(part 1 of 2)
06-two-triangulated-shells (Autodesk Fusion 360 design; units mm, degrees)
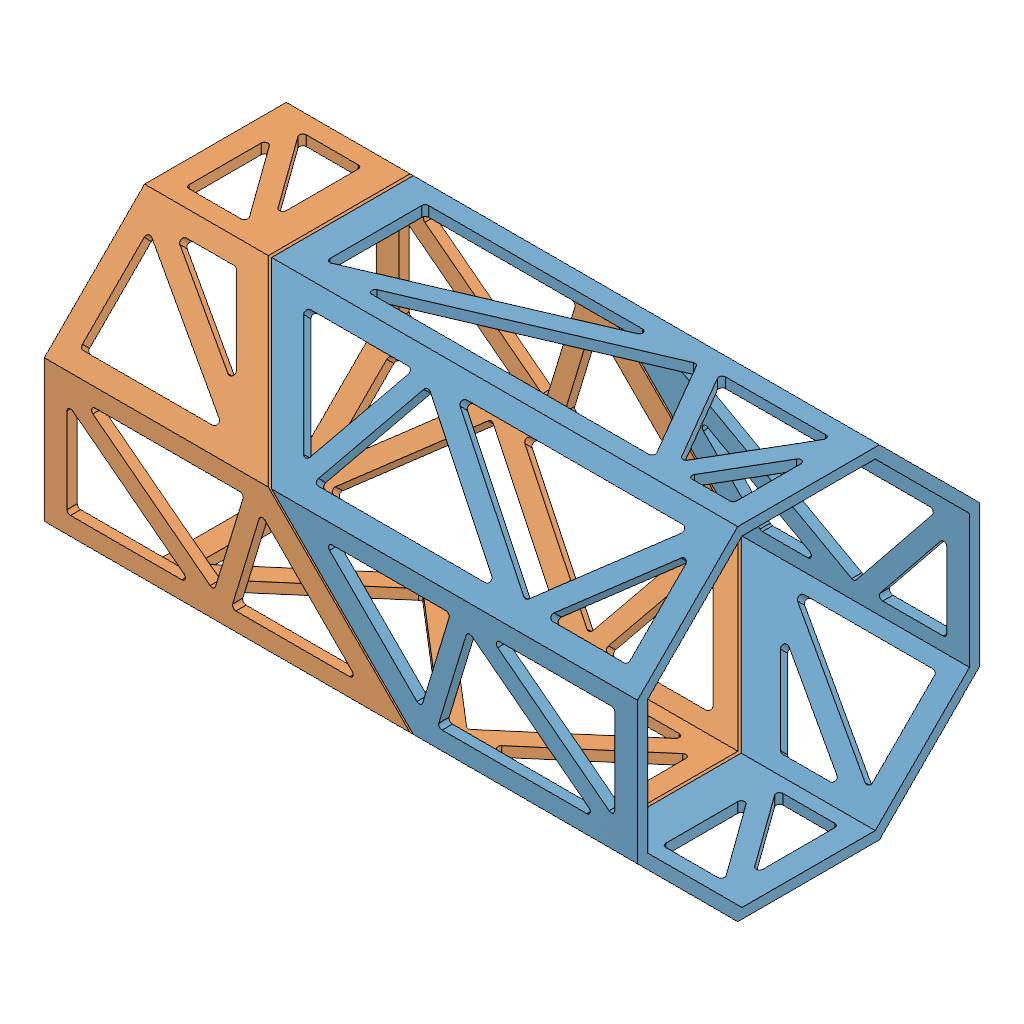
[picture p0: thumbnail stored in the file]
part number: 2026-11-02-20-17-55-344
part number: 2026-11-02-20-17-59-218
part number: 2026-11-02-20-17-59-224
parameter "bodyWidth" = 150 comment "Regular octagon across flats; corner diameter is larger."
parameter "bodyLength" = 260 comment "Overall straight length of the shared master blank."
parameter "splitAngle" = 45 comment "Keep this lesson angle at45 degrees."
parameter "faceGap" = 1 comment "Gap between the two printed joint faces."
parameter "wall" = 4.5 comment "Integrated shell and side brace radial thickness."
parameter "faceHalfWidth" = 31.066 (= "bodyWidth * ( sqrt(2) - 1 ) / 2") comment "Half-width of each outer planar facet."
parameter "memberWidth" = 8 comment "Nominal brace and corner chord width in a facet."
parameter "nodeHalfWidth" = 27.066 (= "faceHalfWidth - memberWidth / 2") comment "Chord centerlines measured from facet center."
parameter "jointNodeQ" = 7 comment "First truss skeleton row from the center joint plane."
parameter "endRim" = 10 comment "Uncut axial rim at each distant end."
parameter "endNodeX" = 124 (= "bodyLength / 2 - endRim + memberWidth / 2") comment "Last skeleton row before aperture inset."
parameter "apertureRadius" = 1.5 comment "Rounded internal corners at triangular openings."
parameter "spokeWidth" = 10 comment "Width of each deep bearing bulkhead spoke."
parameter "spokeDepth" = 18 comment "Bulkhead depth normal to the diagonal joint face."
parameter "carrierOD" = 52 comment "Outside of integrated A front bearing carrier."
parameter "rearCarrierClearance" = 46 comment "Internal carrier relief above front bearing shoulder."
parameter "tubeCornerChamfer" = 0.5 comment "Exposed outside octagon corner bevel."
parameter "tubeRimChamfer" = 0.3 comment "End rim and print-contact edge relief."
parameter "cordStation" = 125 (= "bodyLength / 2 - endRim / 2") comment "Load-test cord port center measured along body X."
parameter "bearingOD" = 22 comment "608 measured outside diameter."
parameter "bearingID" = 8 comment "608 bore."
parameter "bearingWidth" = 7 comment "608 width."
parameter "seatAllowance" = 0.2 comment "Trial DIAMETRAL clearance; choose with printed coupon."
parameter "seatDiameter" = 22.2 (= "bearingOD + seatAllowance") comment "Measured fit controls this."
parameter "coreOD" = 44 comment "Bearing holder outer diameter."
parameter "raceRelief" = 19.5 comment "Outer-ring shoulder opening; verify seals."
parameter "frontSeatDepth" = 7.1 comment "0.1 mm outer-ring axial allowance."
parameter "rearSeatDepth" = 7.2 comment "0.2 mm outer-ring axial float."
parameter "shoulder" = 3 comment "Backing behind each bearing seat."
parameter "supportSpacer" = 12 comment "Purchased metal M3 spacer length."
parameter "supportCircle" = 34 comment "Three M3 support bolts."
parameter "supportSpacerOD" = 6 comment "Purchased spacer outside diameter."
parameter "capThickness" = 3 comment "Both printed outer-ring retaining caps."
parameter "m3Clearance" = 3.3 comment "M3 through holes."
parameter "m4Clearance" = 4.3 comment "M4 through holes."
parameter "qFront" = 0.5 (= "faceGap / 2") comment "Front bearing starts at A mating face."
parameter "qFrontBack" = 10.6 (= "qFront + frontSeatDepth + shoulder") comment "End of integrated A holder."
parameter "qRearBase" = 22.6 (= "qFrontBack + supportSpacer") comment "Start of removable rear holder."
parameter "qRearBearing" = 25.6 (= "qRearBase + shoulder") comment "Rear bearing inner end."
parameter "qRearEnd" = 32.8 (= "qRearBearing + rearSeatDepth") comment "Rear holder outer end."
parameter "bearingSpacing" = 25.1 (= "qRearBearing - qFront") comment "Derived support-center spacing, not a bearing rating."
parameter "mountOD" = 76 comment "B mount and F flange outside diameter."
parameter "mountCircle" = 64 comment "Four M4 attachment holes."
parameter "mountOpening" = 50.3 comment "B through opening."
parameter "hubFace" = -23 comment "Metal hub flat mounting face."
parameter "adapterThickness" = 6 comment "F flange and metal compression sleeve length."
parameter "pilotDiameter" = 50 comment "F shallow centering pilot."
parameter "pilotInside" = 34 comment "Clearance around metal hub."
parameter "pilotHeight" = 2 comment "Short pilot only."
parameter "hubHoleSpacing" = 16 comment "Metal Sonic hub square hole spacing."
parameter "sleeveOD" = 8 comment "M4 metal compression sleeves."
parameter "sleeveAllowance" = 0.2 comment "Trial DIAMETRAL sleeve clearance."
parameter "shaftClearance" = 8.5 comment "F clearance hole; not a bearing."
parameter "nutAF" = 7.2 comment "M4 nominal 7 AF nut trial pocket."
parameter "nutDepth" = 4 comment "Open front M4 nut pocket."
parameter "rootRadius" = 1 comment "Hub-to-wall blend."
parameter "entryChamfer" = 0.4 comment "Assembly lead-in."
parameter "bedRelief" = 0.3 comment "Bed-contact edge allowance."
sketch "01 Master Octagon" plane through (0, 0, 0) normal (1, 0, 0) x axis (0, 0, -1)
  line L1 (31.066, 75) -> (75, 31.066)
  line L2 (-31.066, 75) -> (31.066, 75)
  line L3 (-75, 31.066) -> (-31.066, 75)
  line L4 (-75, -31.066) -> (-75, 31.066)
  line L5 (-31.066, -75) -> (-75, -31.066)
  line L6 (31.066, -75) -> (-31.066, -75)
  line L7 (75, -31.066) -> (31.066, -75)
  line L8 (75, 31.066) -> (75, -31.066)
  point P1 (0, 0)
  point P10 (0, 0)
  point P3 (31.066, 75)
  point P8 (31.066, -75)
  coincident P1 P10
  horizontal L2
  dimension "d59" distance P3 P8 = 150 (= "bodyWidth")
extrude "Extrude1" new body sketch "01 Master Octagon" distance 260 (= "bodyLength")
work_plane "WorkPlane1" RotateAngle 45 (= "splitAngle") ExtraOffset 0
split "Split1"
offset_faces "OffsetFaces1" distance -0.5 (= "-faceGap / 2")
offset_faces "OffsetFaces2" distance -0.5 (= "-faceGap / 2")
component_from_bodies "Body->Comp1"
component_from_bodies "Body->Comp2"
shell "Shell1" innerThickness 4.5 (= "wall")
shell "Shell1" innerThickness 4.5 (= "wall")
work_plane "WorkPlane1" RotateAngle -90 ExtraOffset 0
work_plane "WorkPlane2" AlongDistance 75 (= "bodyWidth / 2") ExtraOffset 0
sketch "A Facet 0 Triangle 1" plane through (0, 75, 0) normal (0, 1, 0) x axis (1, 0, 0)
  line L1 (-65.1005, -27.066) -> (-65.1005, 27.066)
  line L2 (60.9665, 27.066) -> (-65.1005, -27.066)
  line L3 (-65.1005, 27.066) -> (60.9665, 27.066)
  line L4 (-61.1005, -20.9953) -> (-61.1005, 23.066)
  line L5 (41.513, 23.066) -> (-61.1005, -20.9953)
  line L6 (-61.1005, 23.066) -> (41.513, 23.066)
  point P1 (0, 0)
  point P2 (-65.1005, 27.066)
  point P3 (-65.1005, -27.066)
  point P4 (60.9665, 27.066)
  dimension "d72" distance P1 P2 = 65.1005 (= "Linear Dimension-2")
  dimension "d73" distance P1 P2 = 27.066 (= "Linear Dimension-3")
  dimension "d74" distance P1 P3 = 65.1005 (= "Linear Dimension-4")
  dimension "d75" distance P1 P3 = 27.066 (= "Linear Dimension-5")
  dimension "d76" distance P1 P4 = 60.9665 (= "Linear Dimension-6")
  dimension "d77" distance P1 P4 = 27.066 (= "Linear Dimension-7")
  dimension "d78" = -4 (= "-memberWidth / 2")
extrude "Extrude1" cut sketch "A Facet 0 Triangle 1" profile of L5 L6 L4 against normal blind 4.7 (magnitude of "-( wall + 0.2 mm )")
sketch "A Facet 0 Triangle 2" plane through (0, 75, 0) normal (0, 1, 0) x axis (1, 0, 0)
  line L1 (60.9665, 27.066) -> (-65.1005, -27.066)
  line L2 (92.4832, -27.066) -> (60.9665, 27.066)
  line L3 (-65.1005, -27.066) -> (92.4832, -27.066)
  line L4 (59.2912, 21.9935) -> (-45.647, -23.066)
  line L5 (85.5258, -23.066) -> (59.2912, 21.9935)
  line L6 (-45.647, -23.066) -> (85.5258, -23.066)
  point P1 (0, 0)
  point P2 (-65.1005, -27.066)
  point P3 (60.9665, 27.066)
  point P4 (92.4832, -27.066)
  dimension "d81" distance P1 P2 = 65.1005 (= "Linear Dimension-2")
  dimension "d82" distance P1 P2 = 27.066 (= "Linear Dimension-3")
  dimension "d83" distance P1 P3 = 60.9665 (= "Linear Dimension-4")
  dimension "d84" distance P1 P3 = 27.066 (= "Linear Dimension-5")
  dimension "d85" distance P1 P4 = 92.4832 (= "Linear Dimension-6")
  dimension "d86" distance P1 P4 = 27.066 (= "Linear Dimension-7")
  dimension "d87" = 4 (= "memberWidth / 2")
extrude "Extrude2" cut sketch "A Facet 0 Triangle 2" profile of L5 L6 L4 against normal blind 4.7 (magnitude of "-( wall + 0.2 mm )")
sketch "A Facet 0 Triangle 3" plane through (0, 75, 0) normal (0, 1, 0) x axis (1, 0, 0)
  line L1 (92.4832, -27.066) -> (60.9665, 27.066)
  line L2 (124, 27.066) -> (92.4832, -27.066)
  line L3 (60.9665, 27.066) -> (124, 27.066)
  line L4 (92.4832, -19.1161) -> (67.924, 23.066)
  line L5 (117.0425, 23.066) -> (92.4832, -19.1161)
  line L6 (67.924, 23.066) -> (117.0425, 23.066)
  point P1 (0, 0)
  point P2 (60.9665, 27.066)
  point P3 (92.4832, -27.066)
  point P4 (124, 27.066)
  dimension "d90" distance P1 P2 = 60.9665 (= "Linear Dimension-2")
  dimension "d91" distance P1 P2 = 27.066 (= "Linear Dimension-3")
  dimension "d92" distance P1 P3 = 92.4832 (= "Linear Dimension-4")
  dimension "d93" distance P1 P3 = 27.066 (= "Linear Dimension-5")
  dimension "d94" distance P1 P4 = 124 (= "Linear Dimension-6")
  dimension "d95" distance P1 P4 = 27.066 (= "Linear Dimension-7")
  dimension "d96" = -4 (= "-memberWidth / 2")
extrude "Extrude3" cut sketch "A Facet 0 Triangle 3" profile of L5 L6 L4 against normal blind 4.7 (magnitude of "-( wall + 0.2 mm )")
sketch "A Facet 0 Triangle 4" plane through (0, 75, 0) normal (0, 1, 0) x axis (1, 0, 0)
  line L1 (124, 27.066) -> (92.4832, -27.066)
  line L2 (124, -27.066) -> (124, 27.066)
  line L3 (92.4832, -27.066) -> (124, -27.066)
  line L4 (120, 12.2459) -> (99.4407, -23.066)
  line L5 (120, -23.066) -> (120, 12.2459)
  line L6 (99.4407, -23.066) -> (120, -23.066)
  point P1 (0, 0)
  point P2 (92.4832, -27.066)
  point P3 (124, 27.066)
  point P4 (124, -27.066)
  dimension "d99" distance P1 P2 = 92.4832 (= "Linear Dimension-2")
  dimension "d100" distance P1 P2 = 27.066 (= "Linear Dimension-3")
  dimension "d101" distance P1 P3 = 124 (= "Linear Dimension-4")
  dimension "d102" distance P1 P3 = 27.066 (= "Linear Dimension-5")
  dimension "d103" distance P1 P4 = 124 (= "Linear Dimension-6")
  dimension "d104" distance P1 P4 = 27.066 (= "Linear Dimension-7")
  dimension "d105" = 4 (= "memberWidth / 2")
extrude "Extrude4" cut sketch "A Facet 0 Triangle 4" profile of L5 L6 L4 against normal blind 4.7 (magnitude of "-( wall + 0.2 mm )")
fillet "Fillet1" radius 1.5 (= "apertureRadius")
work_plane "WorkPlane3" RotateAngle -45 ExtraOffset 0
work_plane "WorkPlane4" AlongDistance 75 (= "bodyWidth / 2") ExtraOffset 0
sketch "A Facet 45 Triangle 1" plane through (0, 53.033, 53.033) normal (0, 0.7071, 0.7071) x axis (1, 0, 0)
  line L1 (-23.9949, -27.066) -> (-62.2721, 27.066)
  line L2 (-0.1814, 27.066) -> (-23.9949, -27.066)
  line L3 (-62.2721, 27.066) -> (-0.1814, 27.066)
  line L4 (-24.81, -18.9852) -> (-54.5447, 23.066)
  line L5 (-6.311, 23.066) -> (-24.81, -18.9852)
  line L6 (-54.5447, 23.066) -> (-6.311, 23.066)
  point P1 (0, 0)
  point P2 (-62.2721, 27.066)
  point P3 (-23.9949, -27.066)
  point P4 (-0.1814, 27.066)
  dimension "d114" distance P1 P2 = 62.2721 (= "Linear Dimension-2")
  dimension "d115" distance P1 P2 = 27.066 (= "Linear Dimension-3")
  dimension "d116" distance P1 P3 = 23.9949 (= "Linear Dimension-4")
  dimension "d117" distance P1 P3 = 27.066 (= "Linear Dimension-5")
  dimension "d118" distance P1 P4 = 0.1814 (= "Linear Dimension-6")
  dimension "d119" distance P1 P4 = 27.066 (= "Linear Dimension-7")
  dimension "d120" = -4 (= "-memberWidth / 2")
extrude "Extrude5" cut sketch "A Facet 45 Triangle 1" profile of L5 L6 L4 against normal blind 4.7 (magnitude of "-( wall + 0.2 mm )")
sketch "A Facet 45 Triangle 2" plane through (0, 53.033, 53.033) normal (0, 0.7071, 0.7071) x axis (1, 0, 0)
  line L1 (-0.1814, 27.066) -> (-23.9949, -27.066)
  line L2 (74.6684, -27.066) -> (-0.1814, 27.066)
  line L3 (-23.9949, -27.066) -> (74.6684, -27.066)
  line L4 (1.4863, 20.9235) -> (-17.8653, -23.066)
  line L5 (62.3117, -23.066) -> (1.4863, 20.9235)
  line L6 (-17.8653, -23.066) -> (62.3117, -23.066)
  point P1 (0, 0)
  point P2 (-23.9949, -27.066)
  point P3 (-0.1814, 27.066)
  point P4 (74.6684, -27.066)
  dimension "d123" distance P1 P2 = 23.9949 (= "Linear Dimension-2")
  dimension "d124" distance P1 P2 = 27.066 (= "Linear Dimension-3")
  dimension "d125" distance P1 P3 = 0.1814 (= "Linear Dimension-4")
  dimension "d126" distance P1 P3 = 27.066 (= "Linear Dimension-5")
  dimension "d127" distance P1 P4 = 74.6684 (= "Linear Dimension-6")
  dimension "d128" distance P1 P4 = 27.066 (= "Linear Dimension-7")
  dimension "d129" = 4 (= "memberWidth / 2")
extrude "Extrude6" cut sketch "A Facet 45 Triangle 2" profile of L5 L6 L4 against normal blind 4.7 (magnitude of "-( wall + 0.2 mm )")
sketch "A Facet 45 Triangle 3" plane through (0, 53.033, 53.033) normal (0, 0.7071, 0.7071) x axis (1, 0, 0)
  line L1 (74.6684, -27.066) -> (-0.1814, 27.066)
  line L2 (124, 27.066) -> (74.6684, -27.066)
  line L3 (-0.1814, 27.066) -> (124, 27.066)
  line L4 (74.1179, -21.7315) -> (12.1753, 23.066)
  line L5 (114.9429, 23.066) -> (74.1179, -21.7315)
  line L6 (12.1753, 23.066) -> (114.9429, 23.066)
  point P1 (0, 0)
  point P2 (-0.1814, 27.066)
  point P3 (74.6684, -27.066)
  point P4 (124, 27.066)
  dimension "d132" distance P1 P2 = 0.1814 (= "Linear Dimension-2")
  dimension "d133" distance P1 P2 = 27.066 (= "Linear Dimension-3")
  dimension "d134" distance P1 P3 = 74.6684 (= "Linear Dimension-4")
  dimension "d135" distance P1 P3 = 27.066 (= "Linear Dimension-5")
  dimension "d136" distance P1 P4 = 124 (= "Linear Dimension-6")
  dimension "d137" distance P1 P4 = 27.066 (= "Linear Dimension-7")
  dimension "d138" = -4 (= "-memberWidth / 2")
extrude "Extrude7" cut sketch "A Facet 45 Triangle 3" profile of L5 L6 L4 against normal blind 4.7 (magnitude of "-( wall + 0.2 mm )")
sketch "A Facet 45 Triangle 4" plane through (0, 53.033, 53.033) normal (0, 0.7071, 0.7071) x axis (1, 0, 0)
  line L1 (124, 27.066) -> (74.6684, -27.066)
  line L2 (124, -27.066) -> (124, 27.066)
  line L3 (74.6684, -27.066) -> (124, -27.066)
  line L4 (120, 16.7383) -> (83.7255, -23.066)
  line L5 (120, -23.066) -> (120, 16.7383)
  line L6 (83.7255, -23.066) -> (120, -23.066)
  point P1 (0, 0)
  point P2 (74.6684, -27.066)
  point P3 (124, 27.066)
  point P4 (124, -27.066)
  dimension "d141" distance P1 P2 = 74.6684 (= "Linear Dimension-2")
  dimension "d142" distance P1 P2 = 27.066 (= "Linear Dimension-3")
  dimension "d143" distance P1 P3 = 124 (= "Linear Dimension-4")
  dimension "d144" distance P1 P3 = 27.066 (= "Linear Dimension-5")
  dimension "d145" distance P1 P4 = 124 (= "Linear Dimension-6")
  dimension "d146" distance P1 P4 = 27.066 (= "Linear Dimension-7")
  dimension "d147" = 4 (= "memberWidth / 2")
extrude "Extrude8" cut sketch "A Facet 45 Triangle 4" profile of L5 L6 L4 against normal blind 4.7 (magnitude of "-( wall + 0.2 mm )")
fillet "Fillet2" radius 1.5 (= "apertureRadius")
work_plane "WorkPlane5" RotateAngle 0 ExtraOffset 0
work_plane "WorkPlane6" AlongDistance 75 (= "bodyWidth / 2") ExtraOffset 0
sketch "A Facet 90 Triangle 1" plane through (0, 0, 75) normal (0, 0, 1) x axis (1, 0, 0)
  line L1 (36.9655, -27.066) -> (-17.1665, 27.066)
  line L2 (53.4167, 27.066) -> (36.9655, -27.066)
  line L3 (-17.1665, 27.066) -> (53.4167, 27.066)
  line L4 (35.0777, -19.5214) -> (-7.5097, 23.066)
  line L5 (48.0205, 23.066) -> (35.0777, -19.5214)
  line L6 (-7.5097, 23.066) -> (48.0205, 23.066)
  point P1 (0, 0)
  point P2 (-17.1665, 27.066)
  point P3 (36.9655, -27.066)
  point P4 (53.4167, 27.066)
  dimension "d156" distance P1 P2 = 17.1665 (= "Linear Dimension-2")
  dimension "d157" distance P1 P2 = 27.066 (= "Linear Dimension-3")
  dimension "d158" distance P1 P3 = 36.9655 (= "Linear Dimension-4")
  dimension "d159" distance P1 P3 = 27.066 (= "Linear Dimension-5")
  dimension "d160" distance P1 P4 = 53.4167 (= "Linear Dimension-6")
  dimension "d161" distance P1 P4 = 27.066 (= "Linear Dimension-7")
  dimension "d162" = -4 (= "-memberWidth / 2")
extrude "Extrude9" cut sketch "A Facet 90 Triangle 1" profile of L5 L6 L4 against normal blind 4.7 (magnitude of "-( wall + 0.2 mm )")
sketch "A Facet 90 Triangle 2" plane through (0, 0, 75) normal (0, 0, 1) x axis (1, 0, 0)
  line L1 (53.4167, 27.066) -> (36.9655, -27.066)
  line L2 (124, -27.066) -> (53.4167, 27.066)
  line L3 (36.9655, -27.066) -> (124, -27.066)
  line L4 (55.5648, 20.3777) -> (42.3618, -23.066)
  line L5 (112.2115, -23.066) -> (55.5648, 20.3777)
  line L6 (42.3618, -23.066) -> (112.2115, -23.066)
  point P1 (0, 0)
  point P2 (36.9655, -27.066)
  point P3 (53.4167, 27.066)
  point P4 (124, -27.066)
  dimension "d165" distance P1 P2 = 36.9655 (= "Linear Dimension-2")
  dimension "d166" distance P1 P2 = 27.066 (= "Linear Dimension-3")
  dimension "d167" distance P1 P3 = 53.4167 (= "Linear Dimension-4")
  dimension "d168" distance P1 P3 = 27.066 (= "Linear Dimension-5")
  dimension "d169" distance P1 P4 = 124 (= "Linear Dimension-6")
  dimension "d170" distance P1 P4 = 27.066 (= "Linear Dimension-7")
  dimension "d171" = 4 (= "memberWidth / 2")
extrude "Extrude10" cut sketch "A Facet 90 Triangle 2" profile of L5 L6 L4 against normal blind 4.7 (magnitude of "-( wall + 0.2 mm )")
sketch "A Facet 90 Triangle 3" plane through (0, 0, 75) normal (0, 0, 1) x axis (1, 0, 0)
  line L1 (124, -27.066) -> (53.4167, 27.066)
  line L2 (124, 27.066) -> (124, -27.066)
  line L3 (53.4167, 27.066) -> (124, 27.066)
  line L4 (120, -18.9574) -> (65.2053, 23.066)
  line L5 (120, 23.066) -> (120, -18.9574)
  line L6 (65.2053, 23.066) -> (120, 23.066)
  point P1 (0, 0)
  point P2 (53.4167, 27.066)
  point P3 (124, -27.066)
  point P4 (124, 27.066)
  dimension "d174" distance P1 P2 = 53.4167 (= "Linear Dimension-2")
  dimension "d175" distance P1 P2 = 27.066 (= "Linear Dimension-3")
  dimension "d176" distance P1 P3 = 124 (= "Linear Dimension-4")
  dimension "d177" distance P1 P3 = 27.066 (= "Linear Dimension-5")
  dimension "d178" distance P1 P4 = 124 (= "Linear Dimension-6")
  dimension "d179" distance P1 P4 = 27.066 (= "Linear Dimension-7")
  dimension "d180" = -4 (= "-memberWidth / 2")
extrude "Extrude11" cut sketch "A Facet 90 Triangle 3" profile of L5 L6 L4 against normal blind 4.7 (magnitude of "-( wall + 0.2 mm )")
fillet "Fillet3" radius 1.5 (= "apertureRadius")
work_plane "WorkPlane7" RotateAngle 45 ExtraOffset 0
work_plane "WorkPlane8" AlongDistance 75 (= "bodyWidth / 2") ExtraOffset 0
sketch "A Facet 135 Triangle 1" plane through (0, -53.033, 53.033) normal (0, -0.7071, 0.7071) x axis (1, 0, 0)
  line L1 (82.0711, -27.066) -> (43.7939, 27.066)
  line L2 (124, 27.066) -> (82.0711, -27.066)
  line L3 (43.7939, 27.066) -> (124, 27.066)
  line L4 (82.2175, -20.3449) -> (51.5213, 23.066)
  line L5 (115.8422, 23.066) -> (82.2175, -20.3449)
  line L6 (51.5213, 23.066) -> (115.8422, 23.066)
  point P1 (0, 0)
  point P2 (43.7939, 27.066)
  point P3 (82.0711, -27.066)
  point P4 (124, 27.066)
  dimension "d189" distance P1 P2 = 43.7939 (= "Linear Dimension-2")
  dimension "d190" distance P1 P2 = 27.066 (= "Linear Dimension-3")
  dimension "d191" distance P1 P3 = 82.0711 (= "Linear Dimension-4")
  dimension "d192" distance P1 P3 = 27.066 (= "Linear Dimension-5")
  dimension "d193" distance P1 P4 = 124 (= "Linear Dimension-6")
  dimension "d194" distance P1 P4 = 27.066 (= "Linear Dimension-7")
  dimension "d195" = -4 (= "-memberWidth / 2")
extrude "Extrude12" cut sketch "A Facet 135 Triangle 1" profile of L5 L6 L4 against normal blind 4.7 (magnitude of "-( wall + 0.2 mm )")
sketch "A Facet 135 Triangle 2" plane through (0, -53.033, 53.033) normal (0, -0.7071, 0.7071) x axis (1, 0, 0)
  line L1 (124, 27.066) -> (82.0711, -27.066)
  line L2 (124, -27.066) -> (124, 27.066)
  line L3 (82.0711, -27.066) -> (124, -27.066)
  line L4 (120, 15.3697) -> (90.2289, -23.066)
  line L5 (120, -23.066) -> (120, 15.3697)
  line L6 (90.2289, -23.066) -> (120, -23.066)
  point P1 (0, 0)
  point P2 (82.0711, -27.066)
  point P3 (124, 27.066)
  point P4 (124, -27.066)
  dimension "d198" distance P1 P2 = 82.0711 (= "Linear Dimension-2")
  dimension "d199" distance P1 P2 = 27.066 (= "Linear Dimension-3")
  dimension "d200" distance P1 P3 = 124 (= "Linear Dimension-4")
  dimension "d201" distance P1 P3 = 27.066 (= "Linear Dimension-5")
  dimension "d202" distance P1 P4 = 124 (= "Linear Dimension-6")
  dimension "d203" distance P1 P4 = 27.066 (= "Linear Dimension-7")
  dimension "d204" = 4 (= "memberWidth / 2")
extrude "Extrude13" cut sketch "A Facet 135 Triangle 2" profile of L5 L6 L4 against normal blind 4.7 (magnitude of "-( wall + 0.2 mm )")
fillet "Fillet4" radius 1.5 (= "apertureRadius")
work_plane "WorkPlane9" RotateAngle 90 ExtraOffset 0
work_plane "WorkPlane10" AlongDistance 75 (= "bodyWidth / 2") ExtraOffset 0
sketch "A Facet 180 Triangle 1" plane through (0, -75, 0) normal (0, -1, 0) x axis (-1, 0, 0)
  line L1 (-84.8995, 27.066) -> (-84.8995, -27.066)
  line L2 (-124, -27.066) -> (-84.8995, 27.066)
  line L3 (-84.8995, -27.066) -> (-124, -27.066)
  line L4 (-88.8995, 14.697) -> (-88.8995, -23.066)
  line L5 (-116.1764, -23.066) -> (-88.8995, 14.697)
  line L6 (-88.8995, -23.066) -> (-116.1764, -23.066)
  point P1 (0, 0)
  point P2 (-84.8995, -27.066)
  point P3 (-84.8995, 27.066)
  point P4 (-124, -27.066)
  dimension "d213" distance P1 P2 = 84.8995 (= "Linear Dimension-2")
  dimension "d214" distance P1 P2 = 27.066 (= "Linear Dimension-3")
  dimension "d215" distance P1 P3 = 84.8995 (= "Linear Dimension-4")
  dimension "d216" distance P1 P3 = 27.066 (= "Linear Dimension-5")
  dimension "d217" distance P1 P4 = 124 (= "Linear Dimension-6")
  dimension "d218" distance P1 P4 = 27.066 (= "Linear Dimension-7")
  dimension "d219" = -4 (= "-memberWidth / 2")
extrude "Extrude14" cut sketch "A Facet 180 Triangle 1" profile of L5 L6 L4 against normal blind 4.7 (magnitude of "-( wall + 0.2 mm )")
sketch "A Facet 180 Triangle 2" plane through (0, -75, 0) normal (0, -1, 0) x axis (-1, 0, 0)
  line L1 (-124, -27.066) -> (-84.8995, 27.066)
  line L2 (-124, 27.066) -> (-124, -27.066)
  line L3 (-84.8995, 27.066) -> (-124, 27.066)
  line L4 (-120, -14.697) -> (-92.7231, 23.066)
  line L5 (-120, 23.066) -> (-120, -14.697)
  line L6 (-92.7231, 23.066) -> (-120, 23.066)
  point P1 (0, 0)
  point P2 (-84.8995, 27.066)
  point P3 (-124, -27.066)
  point P4 (-124, 27.066)
  dimension "d222" distance P1 P2 = 84.8995 (= "Linear Dimension-2")
  dimension "d223" distance P1 P2 = 27.066 (= "Linear Dimension-3")
  dimension "d224" distance P1 P3 = 124 (= "Linear Dimension-4")
  dimension "d225" distance P1 P3 = 27.066 (= "Linear Dimension-5")
  dimension "d226" distance P1 P4 = 124 (= "Linear Dimension-6")
  dimension "d227" distance P1 P4 = 27.066 (= "Linear Dimension-7")
  dimension "d228" = 4 (= "memberWidth / 2")
extrude "Extrude15" cut sketch "A Facet 180 Triangle 2" profile of L5 L6 L4 against normal blind 4.7 (magnitude of "-( wall + 0.2 mm )")
fillet "Fillet5" radius 1.5 (= "apertureRadius")
work_plane "WorkPlane11" RotateAngle 135 ExtraOffset 0
work_plane "WorkPlane12" AlongDistance 75 (= "bodyWidth / 2") ExtraOffset 0
sketch "A Facet 225 Triangle 1" plane through (0, -53.033, -53.033) normal (0, -0.7071, -0.7071) x axis (1, 0, 0)
  line L1 (43.7939, -27.066) -> (82.0711, 27.066)
  line L2 (124, 27.066) -> (43.7939, -27.066)
  line L3 (82.0711, 27.066) -> (124, 27.066)
  line L4 (59.6927, -11.51) -> (84.1416, 23.066)
  line L5 (110.9231, 23.066) -> (59.6927, -11.51)
  line L6 (84.1416, 23.066) -> (110.9231, 23.066)
  point P1 (0, 0)
  point P2 (82.0711, 27.066)
  point P3 (43.7939, -27.066)
  point P4 (124, 27.066)
  dimension "d237" distance P1 P2 = 82.0711 (= "Linear Dimension-2")
  dimension "d238" distance P1 P2 = 27.066 (= "Linear Dimension-3")
  dimension "d239" distance P1 P3 = 43.7939 (= "Linear Dimension-4")
  dimension "d240" distance P1 P3 = 27.066 (= "Linear Dimension-5")
  dimension "d241" distance P1 P4 = 124 (= "Linear Dimension-6")
  dimension "d242" distance P1 P4 = 27.066 (= "Linear Dimension-7")
  dimension "d243" = -4 (= "-memberWidth / 2")
extrude "Extrude16" cut sketch "A Facet 225 Triangle 1" profile of L5 L6 L4 against normal blind 4.7 (magnitude of "-( wall + 0.2 mm )")
sketch "A Facet 225 Triangle 2" plane through (0, -53.033, -53.033) normal (0, -0.7071, -0.7071) x axis (1, 0, 0)
  line L1 (124, 27.066) -> (43.7939, -27.066)
  line L2 (124, -27.066) -> (124, 27.066)
  line L3 (43.7939, -27.066) -> (124, -27.066)
  line L4 (120, 19.5406) -> (56.8709, -23.066)
  line L5 (120, -23.066) -> (120, 19.5406)
  line L6 (56.8709, -23.066) -> (120, -23.066)
  point P1 (0, 0)
  point P2 (43.7939, -27.066)
  point P3 (124, 27.066)
  point P4 (124, -27.066)
  dimension "d246" distance P1 P2 = 43.7939 (= "Linear Dimension-2")
  dimension "d247" distance P1 P2 = 27.066 (= "Linear Dimension-3")
  dimension "d248" distance P1 P3 = 124 (= "Linear Dimension-4")
  dimension "d249" distance P1 P3 = 27.066 (= "Linear Dimension-5")
  dimension "d250" distance P1 P4 = 124 (= "Linear Dimension-6")
  dimension "d251" distance P1 P4 = 27.066 (= "Linear Dimension-7")
  dimension "d252" = 4 (= "memberWidth / 2")
extrude "Extrude17" cut sketch "A Facet 225 Triangle 2" profile of L5 L6 L4 against normal blind 4.7 (magnitude of "-( wall + 0.2 mm )")
fillet "Fillet6" radius 1.5 (= "apertureRadius")
work_plane "WorkPlane13" RotateAngle 180 ExtraOffset 0
work_plane "WorkPlane14" AlongDistance 75 (= "bodyWidth / 2") ExtraOffset 0
sketch "A Facet 270 Triangle 1" plane through (0, 0, -75) normal (0, 0, -1) x axis (-1, 0, 0)
  line L1 (17.1665, 27.066) -> (-36.9655, -27.066)
  line L2 (-80.4828, -27.066) -> (17.1665, 27.066)
  line L3 (-36.9655, -27.066) -> (-80.4828, -27.066)
  line L4 (-5.7896, 9.7668) -> (-38.6224, -23.066)
  line L5 (-65.0169, -23.066) -> (-5.7896, 9.7668)
  line L6 (-38.6224, -23.066) -> (-65.0169, -23.066)
  point P1 (0, 0)
  point P2 (-36.9655, -27.066)
  point P3 (17.1665, 27.066)
  point P4 (-80.4828, -27.066)
  dimension "d261" distance P1 P2 = 36.9655 (= "Linear Dimension-2")
  dimension "d262" distance P1 P2 = 27.066 (= "Linear Dimension-3")
  dimension "d263" distance P1 P3 = 17.1665 (= "Linear Dimension-4")
  dimension "d264" distance P1 P3 = 27.066 (= "Linear Dimension-5")
  dimension "d265" distance P1 P4 = 80.4828 (= "Linear Dimension-6")
  dimension "d266" distance P1 P4 = 27.066 (= "Linear Dimension-7")
  dimension "d267" = -4 (= "-memberWidth / 2")
extrude "Extrude18" cut sketch "A Facet 270 Triangle 1" profile of L5 L6 L4 against normal blind 4.7 (magnitude of "-( wall + 0.2 mm )")
sketch "A Facet 270 Triangle 2" plane through (0, 0, -75) normal (0, 0, -1) x axis (-1, 0, 0)
  line L1 (-80.4828, -27.066) -> (17.1665, 27.066)
  line L2 (-124, 27.066) -> (-80.4828, -27.066)
  line L3 (17.1665, 27.066) -> (-124, 27.066)
  line L4 (-79.4759, -21.9343) -> (1.7007, 23.066)
  line L5 (-115.6521, 23.066) -> (-79.4759, -21.9343)
  line L6 (1.7007, 23.066) -> (-115.6521, 23.066)
  point P1 (0, 0)
  point P2 (17.1665, 27.066)
  point P3 (-80.4828, -27.066)
  point P4 (-124, 27.066)
  dimension "d270" distance P1 P2 = 17.1665 (= "Linear Dimension-2")
  dimension "d271" distance P1 P2 = 27.066 (= "Linear Dimension-3")
  dimension "d272" distance P1 P3 = 80.4828 (= "Linear Dimension-4")
  dimension "d273" distance P1 P3 = 27.066 (= "Linear Dimension-5")
  dimension "d274" distance P1 P4 = 124 (= "Linear Dimension-6")
  dimension "d275" distance P1 P4 = 27.066 (= "Linear Dimension-7")
  dimension "d276" = 4 (= "memberWidth / 2")
extrude "Extrude19" cut sketch "A Facet 270 Triangle 2" profile of L5 L6 L4 against normal blind 4.7 (magnitude of "-( wall + 0.2 mm )")
sketch "A Facet 270 Triangle 3" plane through (0, 0, -75) normal (0, 0, -1) x axis (-1, 0, 0)
  line L1 (-124, 27.066) -> (-80.4828, -27.066)
  line L2 (-124, -27.066) -> (-124, 27.066)
  line L3 (-80.4828, -27.066) -> (-124, -27.066)
  line L4 (-120, 15.7062) -> (-88.8307, -23.066)
  line L5 (-120, -23.066) -> (-120, 15.7062)
  line L6 (-88.8307, -23.066) -> (-120, -23.066)
  point P1 (0, 0)
  point P2 (-80.4828, -27.066)
  point P3 (-124, 27.066)
  point P4 (-124, -27.066)
  dimension "d279" distance P1 P2 = 80.4828 (= "Linear Dimension-2")
  dimension "d280" distance P1 P2 = 27.066 (= "Linear Dimension-3")
  dimension "d281" distance P1 P3 = 124 (= "Linear Dimension-4")
  dimension "d282" distance P1 P3 = 27.066 (= "Linear Dimension-5")
  dimension "d283" distance P1 P4 = 124 (= "Linear Dimension-6")
  dimension "d284" distance P1 P4 = 27.066 (= "Linear Dimension-7")
  dimension "d285" = -4 (= "-memberWidth / 2")
extrude "Extrude20" cut sketch "A Facet 270 Triangle 3" profile of L5 L6 L4 against normal blind 4.7 (magnitude of "-( wall + 0.2 mm )")
fillet "Fillet7" radius 1.5 (= "apertureRadius")
work_plane "WorkPlane15" RotateAngle 225 ExtraOffset 0
work_plane "WorkPlane16" AlongDistance 75 (= "bodyWidth / 2") ExtraOffset 0
sketch "A Facet 315 Triangle 1" plane through (0, 53.033, -53.033) normal (0, 0.7071, -0.7071) x axis (1, 0, 0)
  line L1 (-62.2721, -27.066) -> (-23.9949, 27.066)
  line L2 (25.3367, 27.066) -> (-62.2721, -27.066)
  line L3 (-23.9949, 27.066) -> (25.3367, 27.066)
  line L4 (-47.6674, -13.34) -> (-21.9244, 23.066)
  line L5 (11.2532, 23.066) -> (-47.6674, -13.34)
  line L6 (-21.9244, 23.066) -> (11.2532, 23.066)
  point P1 (0, 0)
  point P2 (-23.9949, 27.066)
  point P3 (-62.2721, -27.066)
  point P4 (25.3367, 27.066)
  dimension "d294" distance P1 P2 = 23.9949 (= "Linear Dimension-2")
  dimension "d295" distance P1 P2 = 27.066 (= "Linear Dimension-3")
  dimension "d296" distance P1 P3 = 62.2721 (= "Linear Dimension-4")
  dimension "d297" distance P1 P3 = 27.066 (= "Linear Dimension-5")
  dimension "d298" distance P1 P4 = 25.3367 (= "Linear Dimension-6")
  dimension "d299" distance P1 P4 = 27.066 (= "Linear Dimension-7")
  dimension "d300" = -4 (= "-memberWidth / 2")
extrude "Extrude21" cut sketch "A Facet 315 Triangle 1" profile of L5 L6 L4 against normal blind 4.7 (magnitude of "-( wall + 0.2 mm )")
sketch "A Facet 315 Triangle 2" plane through (0, 53.033, -53.033) normal (0, 0.7071, -0.7071) x axis (1, 0, 0)
  line L1 (25.3367, 27.066) -> (-62.2721, -27.066)
  line L2 (61.9093, -27.066) -> (25.3367, 27.066)
  line L3 (-62.2721, -27.066) -> (61.9093, -27.066)
  line L4 (24.1722, 21.6445) -> (-48.1886, -23.066)
  line L5 (54.3795, -23.066) -> (24.1722, 21.6445)
  line L6 (-48.1886, -23.066) -> (54.3795, -23.066)
  point P1 (0, 0)
  point P2 (-62.2721, -27.066)
  point P3 (25.3367, 27.066)
  point P4 (61.9093, -27.066)
  dimension "d303" distance P1 P2 = 62.2721 (= "Linear Dimension-2")
  dimension "d304" distance P1 P2 = 27.066 (= "Linear Dimension-3")
  dimension "d305" distance P1 P3 = 25.3367 (= "Linear Dimension-4")
  dimension "d306" distance P1 P3 = 27.066 (= "Linear Dimension-5")
  dimension "d307" distance P1 P4 = 61.9093 (= "Linear Dimension-6")
  dimension "d308" distance P1 P4 = 27.066 (= "Linear Dimension-7")
  dimension "d309" = 4 (= "memberWidth / 2")
extrude "Extrude22" cut sketch "A Facet 315 Triangle 2" profile of L5 L6 L4 against normal blind 4.7 (magnitude of "-( wall + 0.2 mm )")
sketch "A Facet 315 Triangle 3" plane through (0, 53.033, -53.033) normal (0, 0.7071, -0.7071) x axis (1, 0, 0)
  line L1 (61.9093, -27.066) -> (25.3367, 27.066)
  line L2 (124, 27.066) -> (61.9093, -27.066)
  line L3 (25.3367, 27.066) -> (124, 27.066)
  line L4 (62.6909, -21.0779) -> (32.8665, 23.066)
  line L5 (113.325, 23.066) -> (62.6909, -21.0779)
  line L6 (32.8665, 23.066) -> (113.325, 23.066)
  point P1 (0, 0)
  point P2 (25.3367, 27.066)
  point P3 (61.9093, -27.066)
  point P4 (124, 27.066)
  dimension "d312" distance P1 P2 = 25.3367 (= "Linear Dimension-2")
  dimension "d313" distance P1 P2 = 27.066 (= "Linear Dimension-3")
  dimension "d314" distance P1 P3 = 61.9093 (= "Linear Dimension-4")
  dimension "d315" distance P1 P3 = 27.066 (= "Linear Dimension-5")
  dimension "d316" distance P1 P4 = 124 (= "Linear Dimension-6")
  dimension "d317" distance P1 P4 = 27.066 (= "Linear Dimension-7")
  dimension "d318" = -4 (= "-memberWidth / 2")
extrude "Extrude23" cut sketch "A Facet 315 Triangle 3" profile of L5 L6 L4 against normal blind 4.7 (magnitude of "-( wall + 0.2 mm )")
sketch "A Facet 315 Triangle 4" plane through (0, 53.033, -53.033) normal (0, 0.7071, -0.7071) x axis (1, 0, 0)
  line L1 (124, 27.066) -> (61.9093, -27.066)
  line L2 (124, -27.066) -> (124, 27.066)
  line L3 (61.9093, -27.066) -> (124, -27.066)
  line L4 (120, 18.272) -> (72.5843, -23.066)
  line L5 (120, -23.066) -> (120, 18.272)
  line L6 (72.5843, -23.066) -> (120, -23.066)
  point P1 (0, 0)
  point P2 (61.9093, -27.066)
  point P3 (124, 27.066)
  point P4 (124, -27.066)
  dimension "d321" distance P1 P2 = 61.9093 (= "Linear Dimension-2")
  dimension "d322" distance P1 P2 = 27.066 (= "Linear Dimension-3")
  dimension "d323" distance P1 P3 = 124 (= "Linear Dimension-4")
  dimension "d324" distance P1 P3 = 27.066 (= "Linear Dimension-5")
  dimension "d325" distance P1 P4 = 124 (= "Linear Dimension-6")
  dimension "d326" distance P1 P4 = 27.066 (= "Linear Dimension-7")
  dimension "d327" = 4 (= "memberWidth / 2")
extrude "Extrude24" cut sketch "A Facet 315 Triangle 4" profile of L5 L6 L4 against normal blind 4.7 (magnitude of "-( wall + 0.2 mm )")
fillet "Fillet8" radius 1.5 (= "apertureRadius")
work_plane "WorkPlane1" RotateAngle -90 ExtraOffset 0
work_plane "WorkPlane2" AlongDistance 75 (= "bodyWidth / 2") ExtraOffset 0
sketch "B Facet 0 Triangle 1" plane through (0, 75, 0) normal (0, 1, 0) x axis (1, 0, 0)
  line L1 (-84.8995, -27.066) -> (-84.8995, 27.066)
  line L2 (-124, 27.066) -> (-84.8995, -27.066)
  line L3 (-84.8995, 27.066) -> (-124, 27.066)
  line L4 (-88.8995, -14.697) -> (-88.8995, 23.066)
  line L5 (-116.1764, 23.066) -> (-88.8995, -14.697)
  line L6 (-88.8995, 23.066) -> (-116.1764, 23.066)
  point P1 (0, 0)
  point P2 (-84.8995, 27.066)
  point P3 (-84.8995, -27.066)
  point P4 (-124, 27.066)
  dimension "d336" distance P1 P2 = 84.8995 (= "Linear Dimension-2")
  dimension "d337" distance P1 P2 = 27.066 (= "Linear Dimension-3")
  dimension "d338" distance P1 P3 = 84.8995 (= "Linear Dimension-4")
  dimension "d339" distance P1 P3 = 27.066 (= "Linear Dimension-5")
  dimension "d340" distance P1 P4 = 124 (= "Linear Dimension-6")
  dimension "d341" distance P1 P4 = 27.066 (= "Linear Dimension-7")
  dimension "d342" = 4 (= "memberWidth / 2")
extrude "Extrude1" cut sketch "B Facet 0 Triangle 1" profile of L5 L6 L4 against normal blind 4.7 (magnitude of "-( wall + 0.2 mm )")
sketch "B Facet 0 Triangle 2" plane through (0, 75, 0) normal (0, 1, 0) x axis (1, 0, 0)
  line L1 (-124, 27.066) -> (-84.8995, -27.066)
  line L2 (-124, -27.066) -> (-124, 27.066)
  line L3 (-84.8995, -27.066) -> (-124, -27.066)
  line L4 (-120, 14.697) -> (-92.7231, -23.066)
  line L5 (-120, -23.066) -> (-120, 14.697)
  line L6 (-92.7231, -23.066) -> (-120, -23.066)
  point P1 (0, 0)
  point P2 (-84.8995, -27.066)
  point P3 (-124, 27.066)
  point P4 (-124, -27.066)
  dimension "d345" distance P1 P2 = 84.8995 (= "Linear Dimension-2")
  dimension "d346" distance P1 P2 = 27.066 (= "Linear Dimension-3")
  dimension "d347" distance P1 P3 = 124 (= "Linear Dimension-4")
  dimension "d348" distance P1 P3 = 27.066 (= "Linear Dimension-5")
  dimension "d349" distance P1 P4 = 124 (= "Linear Dimension-6")
  dimension "d350" distance P1 P4 = 27.066 (= "Linear Dimension-7")
  dimension "d351" = -4 (= "-memberWidth / 2")
extrude "Extrude2" cut sketch "B Facet 0 Triangle 2" profile of L5 L6 L4 against normal blind 4.7 (magnitude of "-( wall + 0.2 mm )")
fillet "Fillet1" radius 1.5 (= "apertureRadius")
work_plane "WorkPlane3" RotateAngle -45 ExtraOffset 0
work_plane "WorkPlane4" AlongDistance 75 (= "bodyWidth / 2") ExtraOffset 0
sketch "B Facet 45 Triangle 1" plane through (0, 53.033, 53.033) normal (0, 0.7071, 0.7071) x axis (1, 0, 0)
  line L1 (-43.7939, -27.066) -> (-82.0711, 27.066)
  line L2 (-124, 27.066) -> (-43.7939, -27.066)
  line L3 (-82.0711, 27.066) -> (-124, 27.066)
  line L4 (-59.6927, -11.51) -> (-84.1416, 23.066)
  line L5 (-110.9231, 23.066) -> (-59.6927, -11.51)
  line L6 (-84.1416, 23.066) -> (-110.9231, 23.066)
  point P1 (0, 0)
  point P2 (-82.0711, 27.066)
  point P3 (-43.7939, -27.066)
  point P4 (-124, 27.066)
  dimension "d360" distance P1 P2 = 82.0711 (= "Linear Dimension-2")
  dimension "d361" distance P1 P2 = 27.066 (= "Linear Dimension-3")
  dimension "d362" distance P1 P3 = 43.7939 (= "Linear Dimension-4")
  dimension "d363" distance P1 P3 = 27.066 (= "Linear Dimension-5")
  dimension "d364" distance P1 P4 = 124 (= "Linear Dimension-6")
  dimension "d365" distance P1 P4 = 27.066 (= "Linear Dimension-7")
  dimension "d366" = 4 (= "memberWidth / 2")
extrude "Extrude3" cut sketch "B Facet 45 Triangle 1" profile of L5 L6 L4 against normal blind 4.7 (magnitude of "-( wall + 0.2 mm )")
sketch "B Facet 45 Triangle 2" plane through (0, 53.033, 53.033) normal (0, 0.7071, 0.7071) x axis (1, 0, 0)
  line L1 (-124, 27.066) -> (-43.7939, -27.066)
  line L2 (-124, -27.066) -> (-124, 27.066)
  line L3 (-43.7939, -27.066) -> (-124, -27.066)
  line L4 (-120, 19.5406) -> (-56.8709, -23.066)
  line L5 (-120, -23.066) -> (-120, 19.5406)
  line L6 (-56.8709, -23.066) -> (-120, -23.066)
  point P1 (0, 0)
  point P2 (-43.7939, -27.066)
  point P3 (-124, 27.066)
  point P4 (-124, -27.066)
  dimension "d369" distance P1 P2 = 43.7939 (= "Linear Dimension-2")
  dimension "d370" distance P1 P2 = 27.066 (= "Linear Dimension-3")
  dimension "d371" distance P1 P3 = 124 (= "Linear Dimension-4")
  dimension "d372" distance P1 P3 = 27.066 (= "Linear Dimension-5")
  dimension "d373" distance P1 P4 = 124 (= "Linear Dimension-6")
  dimension "d374" distance P1 P4 = 27.066 (= "Linear Dimension-7")
  dimension "d375" = -4 (= "-memberWidth / 2")
extrude "Extrude4" cut sketch "B Facet 45 Triangle 2" profile of L5 L6 L4 against normal blind 4.7 (magnitude of "-( wall + 0.2 mm )")
fillet "Fillet2" radius 1.5 (= "apertureRadius")
work_plane "WorkPlane5" RotateAngle 0 ExtraOffset 0
work_plane "WorkPlane6" AlongDistance 75 (= "bodyWidth / 2") ExtraOffset 0
sketch "B Facet 90 Triangle 1" plane through (0, 0, 75) normal (0, 0, 1) x axis (1, 0, 0)
  line L1 (-36.9655, 27.066) -> (17.1665, -27.066)
  line L2 (-53.4167, -27.066) -> (-36.9655, 27.066)
  line L3 (17.1665, -27.066) -> (-53.4167, -27.066)
  line L4 (-35.0777, 19.5214) -> (7.5097, -23.066)
  line L5 (-48.0205, -23.066) -> (-35.0777, 19.5214)
  line L6 (7.5097, -23.066) -> (-48.0205, -23.066)
  point P1 (0, 0)
  point P2 (17.1665, -27.066)
  point P3 (-36.9655, 27.066)
  point P4 (-53.4167, -27.066)
  dimension "d384" distance P1 P2 = 17.1665 (= "Linear Dimension-2")
  dimension "d385" distance P1 P2 = 27.066 (= "Linear Dimension-3")
  dimension "d386" distance P1 P3 = 36.9655 (= "Linear Dimension-4")
  dimension "d387" distance P1 P3 = 27.066 (= "Linear Dimension-5")
  dimension "d388" distance P1 P4 = 53.4167 (= "Linear Dimension-6")
  dimension "d389" distance P1 P4 = 27.066 (= "Linear Dimension-7")
  dimension "d390" = -4 (= "-memberWidth / 2")
extrude "Extrude5" cut sketch "B Facet 90 Triangle 1" profile of L5 L6 L4 against normal blind 4.7 (magnitude of "-( wall + 0.2 mm )")
sketch "B Facet 90 Triangle 2" plane through (0, 0, 75) normal (0, 0, 1) x axis (1, 0, 0)
  line L1 (-53.4167, -27.066) -> (-36.9655, 27.066)
  line L2 (-124, 27.066) -> (-53.4167, -27.066)
  line L3 (-36.9655, 27.066) -> (-124, 27.066)
  line L4 (-55.5648, -20.3777) -> (-42.3618, 23.066)
  line L5 (-112.2115, 23.066) -> (-55.5648, -20.3777)
  line L6 (-42.3618, 23.066) -> (-112.2115, 23.066)
  point P1 (0, 0)
  point P2 (-36.9655, 27.066)
  point P3 (-53.4167, -27.066)
  point P4 (-124, 27.066)
  dimension "d393" distance P1 P2 = 36.9655 (= "Linear Dimension-2")
  dimension "d394" distance P1 P2 = 27.066 (= "Linear Dimension-3")
  dimension "d395" distance P1 P3 = 53.4167 (= "Linear Dimension-4")
  dimension "d396" distance P1 P3 = 27.066 (= "Linear Dimension-5")
  dimension "d397" distance P1 P4 = 124 (= "Linear Dimension-6")
  dimension "d398" distance P1 P4 = 27.066 (= "Linear Dimension-7")
  dimension "d399" = 4 (= "memberWidth / 2")
extrude "Extrude6" cut sketch "B Facet 90 Triangle 2" profile of L5 L6 L4 against normal blind 4.7 (magnitude of "-( wall + 0.2 mm )")
sketch "B Facet 90 Triangle 3" plane through (0, 0, 75) normal (0, 0, 1) x axis (1, 0, 0)
  line L1 (-124, 27.066) -> (-53.4167, -27.066)
  line L2 (-124, -27.066) -> (-124, 27.066)
  line L3 (-53.4167, -27.066) -> (-124, -27.066)
  line L4 (-120, 18.9574) -> (-65.2053, -23.066)
  line L5 (-120, -23.066) -> (-120, 18.9574)
  line L6 (-65.2053, -23.066) -> (-120, -23.066)
  point P1 (0, 0)
  point P2 (-53.4167, -27.066)
  point P3 (-124, 27.066)
  point P4 (-124, -27.066)
  dimension "d402" distance P1 P2 = 53.4167 (= "Linear Dimension-2")
  dimension "d403" distance P1 P2 = 27.066 (= "Linear Dimension-3")
  dimension "d404" distance P1 P3 = 124 (= "Linear Dimension-4")
  dimension "d405" distance P1 P3 = 27.066 (= "Linear Dimension-5")
  dimension "d406" distance P1 P4 = 124 (= "Linear Dimension-6")
  dimension "d407" distance P1 P4 = 27.066 (= "Linear Dimension-7")
  dimension "d408" = -4 (= "-memberWidth / 2")
extrude "Extrude7" cut sketch "B Facet 90 Triangle 3" profile of L5 L6 L4 against normal blind 4.7 (magnitude of "-( wall + 0.2 mm )")
fillet "Fillet3" radius 1.5 (= "apertureRadius")
work_plane "WorkPlane7" RotateAngle 45 ExtraOffset 0
work_plane "WorkPlane8" AlongDistance 75 (= "bodyWidth / 2") ExtraOffset 0
sketch "B Facet 135 Triangle 1" plane through (0, -53.033, 53.033) normal (0, -0.7071, 0.7071) x axis (1, 0, 0)
  line L1 (62.2721, -27.066) -> (23.9949, 27.066)
  line L2 (-25.3367, 27.066) -> (62.2721, -27.066)
  line L3 (23.9949, 27.066) -> (-25.3367, 27.066)
  line L4 (47.6674, -13.34) -> (21.9244, 23.066)
  line L5 (-11.2532, 23.066) -> (47.6674, -13.34)
  line L6 (21.9244, 23.066) -> (-11.2532, 23.066)
  point P1 (0, 0)
  point P2 (23.9949, 27.066)
  point P3 (62.2721, -27.066)
  point P4 (-25.3367, 27.066)
  dimension "d417" distance P1 P2 = 23.9949 (= "Linear Dimension-2")
  dimension "d418" distance P1 P2 = 27.066 (= "Linear Dimension-3")
  dimension "d419" distance P1 P3 = 62.2721 (= "Linear Dimension-4")
  dimension "d420" distance P1 P3 = 27.066 (= "Linear Dimension-5")
  dimension "d421" distance P1 P4 = 25.3367 (= "Linear Dimension-6")
  dimension "d422" distance P1 P4 = 27.066 (= "Linear Dimension-7")
  dimension "d423" = 4 (= "memberWidth / 2")
extrude "Extrude8" cut sketch "B Facet 135 Triangle 1" profile of L5 L6 L4 against normal blind 4.7 (magnitude of "-( wall + 0.2 mm )")
sketch "B Facet 135 Triangle 2" plane through (0, -53.033, 53.033) normal (0, -0.7071, 0.7071) x axis (1, 0, 0)
  line L1 (-25.3367, 27.066) -> (62.2721, -27.066)
  line L2 (-61.9093, -27.066) -> (-25.3367, 27.066)
  line L3 (62.2721, -27.066) -> (-61.9093, -27.066)
  line L4 (-24.1722, 21.6445) -> (48.1886, -23.066)
  line L5 (-54.3795, -23.066) -> (-24.1722, 21.6445)
  line L6 (48.1886, -23.066) -> (-54.3795, -23.066)
  point P1 (0, 0)
  point P2 (62.2721, -27.066)
  point P3 (-25.3367, 27.066)
  point P4 (-61.9093, -27.066)
  dimension "d426" distance P1 P2 = 62.2721 (= "Linear Dimension-2")
  dimension "d427" distance P1 P2 = 27.066 (= "Linear Dimension-3")
  dimension "d428" distance P1 P3 = 25.3367 (= "Linear Dimension-4")
  dimension "d429" distance P1 P3 = 27.066 (= "Linear Dimension-5")
  dimension "d430" distance P1 P4 = 61.9093 (= "Linear Dimension-6")
  dimension "d431" distance P1 P4 = 27.066 (= "Linear Dimension-7")
  dimension "d432" = -4 (= "-memberWidth / 2")
extrude "Extrude9" cut sketch "B Facet 135 Triangle 2" profile of L5 L6 L4 against normal blind 4.7 (magnitude of "-( wall + 0.2 mm )")
sketch "B Facet 135 Triangle 3" plane through (0, -53.033, 53.033) normal (0, -0.7071, 0.7071) x axis (1, 0, 0)
  line L1 (-61.9093, -27.066) -> (-25.3367, 27.066)
  line L2 (-124, 27.066) -> (-61.9093, -27.066)
  line L3 (-25.3367, 27.066) -> (-124, 27.066)
  line L4 (-62.6909, -21.0779) -> (-32.8665, 23.066)
  line L5 (-113.325, 23.066) -> (-62.6909, -21.0779)
  line L6 (-32.8665, 23.066) -> (-113.325, 23.066)
  point P1 (0, 0)
  point P2 (-25.3367, 27.066)
  point P3 (-61.9093, -27.066)
  point P4 (-124, 27.066)
  dimension "d435" distance P1 P2 = 25.3367 (= "Linear Dimension-2")
  dimension "d436" distance P1 P2 = 27.066 (= "Linear Dimension-3")
  dimension "d437" distance P1 P3 = 61.9093 (= "Linear Dimension-4")
  dimension "d438" distance P1 P3 = 27.066 (= "Linear Dimension-5")
  dimension "d439" distance P1 P4 = 124 (= "Linear Dimension-6")
  dimension "d440" distance P1 P4 = 27.066 (= "Linear Dimension-7")
  dimension "d441" = 4 (= "memberWidth / 2")
extrude "Extrude10" cut sketch "B Facet 135 Triangle 3" profile of L5 L6 L4 against normal blind 4.7 (magnitude of "-( wall + 0.2 mm )")
sketch "B Facet 135 Triangle 4" plane through (0, -53.033, 53.033) normal (0, -0.7071, 0.7071) x axis (1, 0, 0)
  line L1 (-124, 27.066) -> (-61.9093, -27.066)
  line L2 (-124, -27.066) -> (-124, 27.066)
  line L3 (-61.9093, -27.066) -> (-124, -27.066)
  line L4 (-120, 18.272) -> (-72.5843, -23.066)
  line L5 (-120, -23.066) -> (-120, 18.272)
  line L6 (-72.5843, -23.066) -> (-120, -23.066)
  point P1 (0, 0)
  point P2 (-61.9093, -27.066)
  point P3 (-124, 27.066)
  point P4 (-124, -27.066)
  dimension "d444" distance P1 P2 = 61.9093 (= "Linear Dimension-2")
  dimension "d445" distance P1 P2 = 27.066 (= "Linear Dimension-3")
  dimension "d446" distance P1 P3 = 124 (= "Linear Dimension-4")
  dimension "d447" distance P1 P3 = 27.066 (= "Linear Dimension-5")
  dimension "d448" distance P1 P4 = 124 (= "Linear Dimension-6")
  dimension "d449" distance P1 P4 = 27.066 (= "Linear Dimension-7")
  dimension "d450" = -4 (= "-memberWidth / 2")
extrude "Extrude11" cut sketch "B Facet 135 Triangle 4" profile of L5 L6 L4 against normal blind 4.7 (magnitude of "-( wall + 0.2 mm )")
fillet "Fillet4" radius 1.5 (= "apertureRadius")
work_plane "WorkPlane9" RotateAngle 90 ExtraOffset 0
work_plane "WorkPlane10" AlongDistance 75 (= "bodyWidth / 2") ExtraOffset 0
sketch "B Facet 180 Triangle 1" plane through (0, -75, 0) normal (0, -1, 0) x axis (-1, 0, 0)
  line L1 (-65.1005, 27.066) -> (-65.1005, -27.066)
  line L2 (-2.067, -27.066) -> (-65.1005, 27.066)
  line L3 (-65.1005, -27.066) -> (-2.067, -27.066)
  line L4 (-61.1005, 18.3583) -> (-61.1005, -23.066)
  line L5 (-12.8644, -23.066) -> (-61.1005, 18.3583)
  line L6 (-61.1005, -23.066) -> (-12.8644, -23.066)
  point P1 (0, 0)
  point P2 (-65.1005, -27.066)
  point P3 (-65.1005, 27.066)
  point P4 (-2.067, -27.066)
  dimension "d459" distance P1 P2 = 65.1005 (= "Linear Dimension-2")
  dimension "d460" distance P1 P2 = 27.066 (= "Linear Dimension-3")
  dimension "d461" distance P1 P3 = 65.1005 (= "Linear Dimension-4")
  dimension "d462" distance P1 P3 = 27.066 (= "Linear Dimension-5")
  dimension "d463" distance P1 P4 = 2.067 (= "Linear Dimension-6")
  dimension "d464" distance P1 P4 = 27.066 (= "Linear Dimension-7")
  dimension "d465" = 4 (= "memberWidth / 2")
extrude "Extrude12" cut sketch "B Facet 180 Triangle 1" profile of L5 L6 L4 against normal blind 4.7 (magnitude of "-( wall + 0.2 mm )")
sketch "B Facet 180 Triangle 2" plane through (0, -75, 0) normal (0, -1, 0) x axis (-1, 0, 0)
  line L1 (-2.067, -27.066) -> (-65.1005, 27.066)
  line L2 (60.9665, 27.066) -> (-2.067, -27.066)
  line L3 (-65.1005, 27.066) -> (60.9665, 27.066)
  line L4 (-2.067, -21.7934) -> (-54.3031, 23.066)
  line L5 (50.1691, 23.066) -> (-2.067, -21.7934)
  line L6 (-54.3031, 23.066) -> (50.1691, 23.066)
  point P1 (0, 0)
  point P2 (-65.1005, 27.066)
  point P3 (-2.067, -27.066)
  point P4 (60.9665, 27.066)
  dimension "d468" distance P1 P2 = 65.1005 (= "Linear Dimension-2")
  dimension "d469" distance P1 P2 = 27.066 (= "Linear Dimension-3")
  dimension "d470" distance P1 P3 = 2.067 (= "Linear Dimension-4")
  dimension "d471" distance P1 P3 = 27.066 (= "Linear Dimension-5")
  dimension "d472" distance P1 P4 = 60.9665 (= "Linear Dimension-6")
  dimension "d473" distance P1 P4 = 27.066 (= "Linear Dimension-7")
  dimension "d474" = -4 (= "-memberWidth / 2")
extrude "Extrude13" cut sketch "B Facet 180 Triangle 2" profile of L5 L6 L4 against normal blind 4.7 (magnitude of "-( wall + 0.2 mm )")
sketch "B Facet 180 Triangle 3" plane through (0, -75, 0) normal (0, -1, 0) x axis (-1, 0, 0)
  line L1 (60.9665, 27.066) -> (-2.067, -27.066)
  line L2 (124, -27.066) -> (60.9665, 27.066)
  line L3 (-2.067, -27.066) -> (124, -27.066)
  line L4 (60.9665, 21.7934) -> (8.7304, -23.066)
  line L5 (113.2026, -23.066) -> (60.9665, 21.7934)
  line L6 (8.7304, -23.066) -> (113.2026, -23.066)
  point P1 (0, 0)
  point P2 (-2.067, -27.066)
  point P3 (60.9665, 27.066)
  point P4 (124, -27.066)
  dimension "d477" distance P1 P2 = 2.067 (= "Linear Dimension-2")
  dimension "d478" distance P1 P2 = 27.066 (= "Linear Dimension-3")
  dimension "d479" distance P1 P3 = 60.9665 (= "Linear Dimension-4")
  dimension "d480" distance P1 P3 = 27.066 (= "Linear Dimension-5")
  dimension "d481" distance P1 P4 = 124 (= "Linear Dimension-6")
  dimension "d482" distance P1 P4 = 27.066 (= "Linear Dimension-7")
  dimension "d483" = 4 (= "memberWidth / 2")
extrude "Extrude14" cut sketch "B Facet 180 Triangle 3" profile of L5 L6 L4 against normal blind 4.7 (magnitude of "-( wall + 0.2 mm )")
